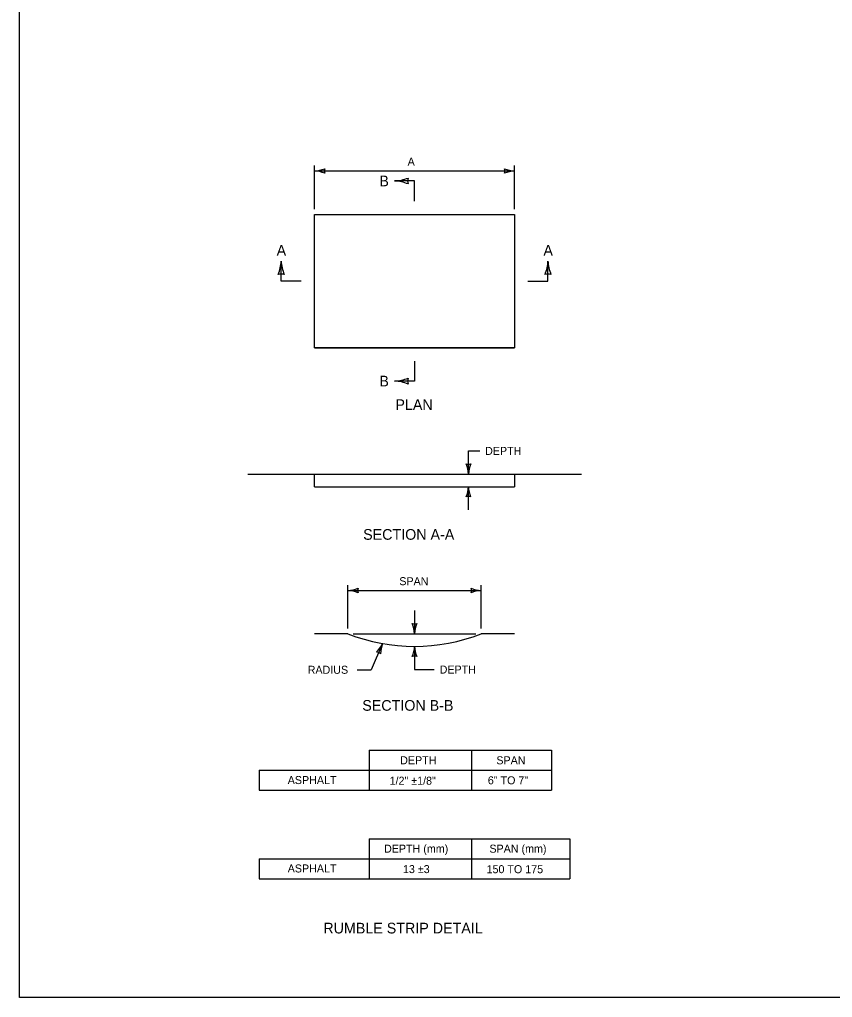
# Model space of a CAD drawing. Extents: x 49937 to 50080, y 49883 to 50108.
# Drawn here: x 49999.38 to 50005.48, y 49987.8 to 49995.13 of the extents above; entities that cross this region are included whole.
import ezdxf

# ---------------------------------------------------------------- set-up
doc = ezdxf.new("R2010")
doc.units = 0
for name, color, linetype in [('Level 1', 7, 'Continuous'), ('Level 2', 7, 'Continuous'), ('Level 3', 7, 'Continuous'), ('Level 6', 7, 'Continuous')]:
    doc.layers.add(name, color=color, linetype=linetype)

msp = doc.modelspace()

# ---------------------------------------------------------------- linework, layer by layer
at = {"layer": 'Level 1'}
for p, q in [((50001.5948, 49992.6697), (50003.0948, 49992.6697)), ((50001.0948, 49991.7227), (50003.5948, 49991.7227)), ((50001.5948, 49991.6277), (50001.5948, 49991.7227)), ((50003.0948, 49991.7227), (50003.0948, 49991.6277)), ((50001.5948, 49991.6277), (50003.0948, 49991.6277)), ((50001.8446, 49990.5256), (50001.5946, 49990.5256)), ((50003.0946, 49990.5256), (50002.8446, 49990.5256))]:
    msp.add_line(p, q, dxfattribs=at)
for points in [[(49999.3835, 49998.9992), (50016.7501, 49998.9992), (50016.7501, 49987.7988), (49999.3835, 49987.7988)], [(50003.0948, 49993.6697), (50003.0948, 49992.6697), (50001.5948, 49992.6697), (50001.5948, 49993.6697)]]:
    msp.add_lwpolyline(points, close=True, dxfattribs=at)
msp.add_arc((50002.3446, 49991.7939), 1.3633, 248.48407, 291.51593, dxfattribs=at)
at = {"layer": 'Level 2'}
for p, q in [((50002.0053, 49989.6517), (50003.3722, 49989.6517)), ((50002.0053, 49989.6517), (50002.0053, 49989.3517)), ((50002.7722, 49989.6517), (50002.7722, 49989.3517)), ((50003.3722, 49989.6517), (50003.3722, 49989.3517)), ((50001.1803, 49989.5017), (50001.1803, 49989.3517)), ((50001.1803, 49989.5017), (50002.0053, 49989.5017)), ((50002.0053, 49989.5017), (50003.3722, 49989.5017)), ((50002.0053, 49989.5017), (50003.3722, 49989.5017)), ((50001.1803, 49989.3517), (50003.3722, 49989.3517)), ((50002.0053, 49989.3517), (50003.3722, 49989.3517)), ((50002.0053, 49988.9891), (50003.5091, 49988.9891)), ((50002.0053, 49988.9891), (50002.0053, 49988.6891)), ((50002.7722, 49988.9891), (50002.7722, 49988.6891)), ((50003.5091, 49988.9891), (50003.5091, 49988.6891)), ((50001.1803, 49988.8391), (50001.1803, 49988.6891)), ((50001.1803, 49988.8391), (50003.5091, 49988.8391)), ((50001.1803, 49988.6891), (50003.5091, 49988.6891))]:
    msp.add_line(p, q, dxfattribs=at)
at = {"layer": 'Level 3'}
for p, q in [((50001.5948, 49993.7097), (50001.5948, 49994.0348)), ((50003.0948, 49993.7097), (50003.0948, 49994.0348)), ((50001.5948, 49993.9948), (50003.0948, 49993.9948)), ((50002.7485, 49991.8961), (50002.8333, 49991.8961)), ((50002.7485, 49991.7227), (50002.7485, 49991.8961)), ((50002.7482, 49991.4543), (50002.7482, 49991.6277)), ((50001.8446, 49990.5656), (50001.8446, 49990.8894)), ((50002.8446, 49990.5656), (50002.8446, 49990.8894)), ((50001.8446, 49990.8494), (50002.8446, 49990.8494)), ((50002.3446, 49990.699), (50002.3446, 49990.5256)), ((50001.8846, 49990.5256), (50002.8046, 49990.5256)), ((50002.105, 49990.4518), (50002.0205, 49990.2553)), ((50002.3446, 49990.4306), (50002.3446, 49990.2572)), ((50001.915, 49990.2553), (50002.0205, 49990.2553)), ((50002.3446, 49990.2572), (50002.4928, 49990.2572))]:
    msp.add_line(p, q, dxfattribs=at)
for centre, radius, start, end in [((50001.5833, 49994.2275), 0.233, 272.82731, 292.07716), ((50001.5857, 49993.7726), 0.2223, 67.45601, 87.63952), ((50001.723, 49993.9948), 0.0548, 162.13882, 197.86118), ((50003.104, 49994.2169), 0.2223, 247.45601, 267.63952), ((50002.9666, 49993.9948), 0.0548, 342.13882, 17.86118), ((50003.1063, 49993.7621), 0.233, 92.82731, 112.07716), ((50002.7485, 49991.8509), 0.0548, 252.13882, 287.86118), ((50002.5158, 49991.7112), 0.233, 2.82731, 22.07716), ((50002.9707, 49991.7136), 0.2223, 157.45601, 177.63952), ((50002.5261, 49991.6369), 0.2223, 337.45601, 357.63952), ((50002.9809, 49991.6392), 0.233, 182.82731, 202.07716), ((50002.7482, 49991.4995), 0.0548, 72.13882, 107.86118), ((50001.8331, 49991.0821), 0.233, 272.82731, 292.07716), ((50001.8355, 49990.6273), 0.2223, 67.45601, 87.63952), ((50001.9728, 49990.8494), 0.0548, 162.13882, 197.86118), ((50002.8538, 49991.0716), 0.2223, 247.45601, 267.63952), ((50002.7164, 49990.8494), 0.0548, 342.13882, 17.86118), ((50002.8561, 49990.6167), 0.233, 92.82731, 112.07716), ((50002.3446, 49990.6538), 0.0548, 252.13882, 287.86118), ((50002.1119, 49990.5141), 0.233, 2.82731, 22.07716), ((50002.5668, 49990.5165), 0.2223, 157.45601, 177.63952), ((50001.9046, 49990.548), 0.2223, 314.19076, 334.37427), ((50002.3234, 49990.3705), 0.233, 159.56206, 178.81191), ((50002.0544, 49990.334), 0.0548, 48.87357, 84.59593), ((50002.1225, 49990.4398), 0.2223, 337.45601, 357.63952), ((50002.5773, 49990.4421), 0.233, 182.82731, 202.07716), ((50002.3446, 49990.3024), 0.0548, 72.13882, 107.86118)]:
    msp.add_arc(centre, radius, start, end, dxfattribs=at)
at = {"layer": 'Level 6'}
for points in [[(50002.3448, 49993.7697), (50002.3448, 49993.9197), (50002.1948, 49993.9197)], [(50001.4948, 49993.1697), (50001.3448, 49993.1697), (50001.3448, 49993.3197)], [(50003.1948, 49993.1697), (50003.3448, 49993.1697), (50003.3448, 49993.3197)], [(50002.3448, 49992.5697), (50002.3448, 49992.4197), (50002.1948, 49992.4197)]]:
    msp.add_lwpolyline(points, dxfattribs=at)
for centre, radius, start, end in [((50002.1795, 49994.23), 0.3107, 272.82731, 292.07716), ((50002.1826, 49993.6235), 0.2964, 67.45601, 87.63952), ((50002.3658, 49993.9197), 0.073, 162.13882, 197.86118), ((50001.0487, 49993.3319), 0.2964, 337.45601, 357.63952), ((50001.6551, 49993.335), 0.3107, 182.82731, 202.07716), ((50003.0487, 49993.3319), 0.2964, 337.45601, 357.63952), ((50003.6551, 49993.335), 0.3107, 182.82731, 202.07716), ((50001.3448, 49993.1487), 0.073, 72.13882, 107.86118), ((50003.3448, 49993.1487), 0.073, 72.13882, 107.86118), ((50002.1795, 49992.73), 0.3107, 272.82731, 292.07716), ((50002.1826, 49992.1235), 0.2964, 67.45601, 87.63952), ((50002.3658, 49992.4197), 0.073, 162.13882, 197.86118)]:
    msp.add_arc(centre, radius, start, end, dxfattribs=at)

# ---------------------------------------------------------------- texts
at = {"layer": 'Level 2'}
for s, height, p in [('A', 0.06, (50002.2926, 49994.0348)), ('B', 0.08, (50002.0808, 49993.8797)), ('A', 0.08, (50001.3105, 49993.3597)), ('A', 0.08, (50003.3105, 49993.3597)), ('B', 0.08, (50002.0808, 49992.3797)), ('PLAN', 0.08, (50002.2012, 49992.203)), ('DEPTH', 0.06, (50002.8733, 49991.8661)), ('SECTION A-A', 0.08, (50001.9591, 49991.23)), ('SPAN', 0.06, (50002.2302, 49990.8894)), ('RADIUS', 0.06, (50001.5434, 49990.2253)), ('DEPTH', 0.06, (50002.5328, 49990.2272)), ('SECTION B-B', 0.08, (50001.9526, 49989.9481)), ('DEPTH', 0.06, (50002.2365, 49989.5469)), ('SPAN', 0.06, (50002.9578, 49989.5467)), ('ASPHALT', 0.06, (50001.3937, 49989.3984)), ('1/2" ±1/8"', 0.06, (50002.1576, 49989.3936)), ('6" TO 7"', 0.06, (50002.8939, 49989.3967)), ('DEPTH (mm)', 0.06, (50002.1159, 49988.8843)), ('SPAN (mm)', 0.06, (50002.9057, 49988.8843)), ('ASPHALT', 0.06, (50001.3937, 49988.7358)), ('13 ±3', 0.06, (50002.2576, 49988.731)), ('150 TO 175', 0.06, (50002.8844, 49988.7303)), ('RUMBLE STRIP DETAIL', 0.08, (50001.6607, 49988.2786))]:
    msp.add_text(s, height=height, dxfattribs=at).set_placement(p)

doc.saveas('drawing.dxf')
